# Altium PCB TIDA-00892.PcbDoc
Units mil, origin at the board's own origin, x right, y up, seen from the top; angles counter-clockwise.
Board outline 1220 x 522 mil, 4 copper layers (Top Layer, GND1, GND2, Bottom Layer), stack 63.756 mil thick; 26 components, 22 nets, 75 pads, 28 vias.
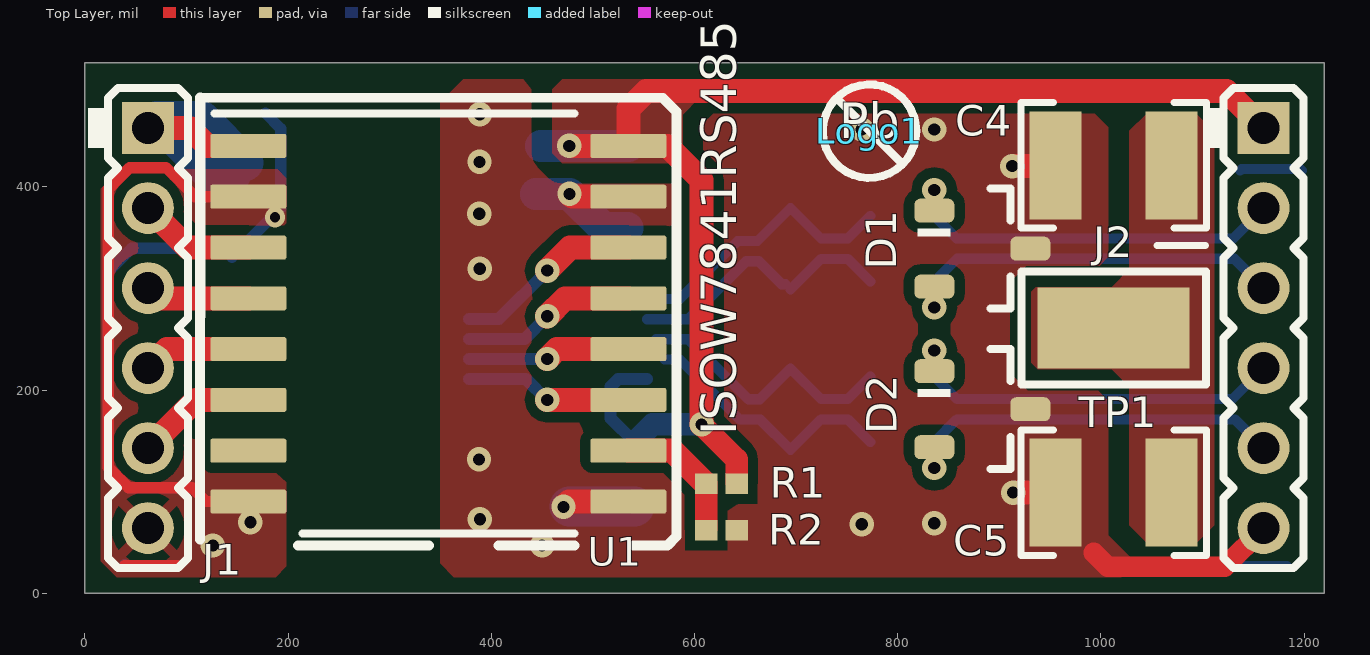
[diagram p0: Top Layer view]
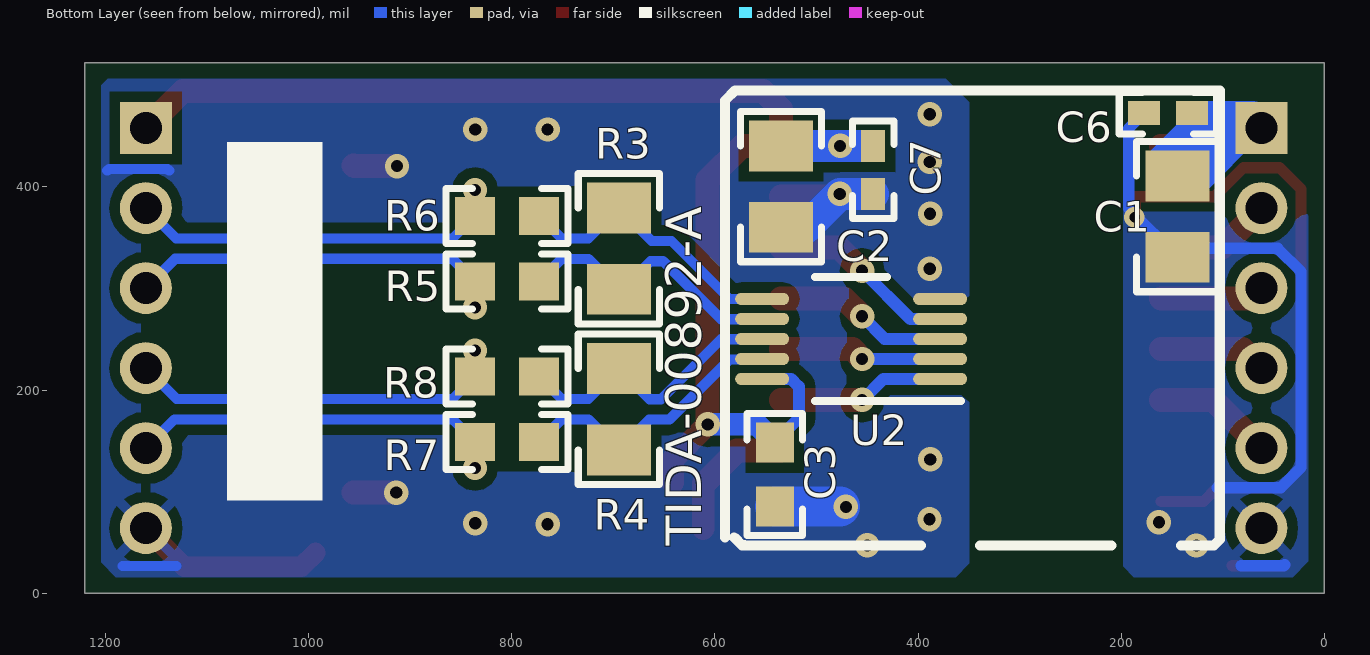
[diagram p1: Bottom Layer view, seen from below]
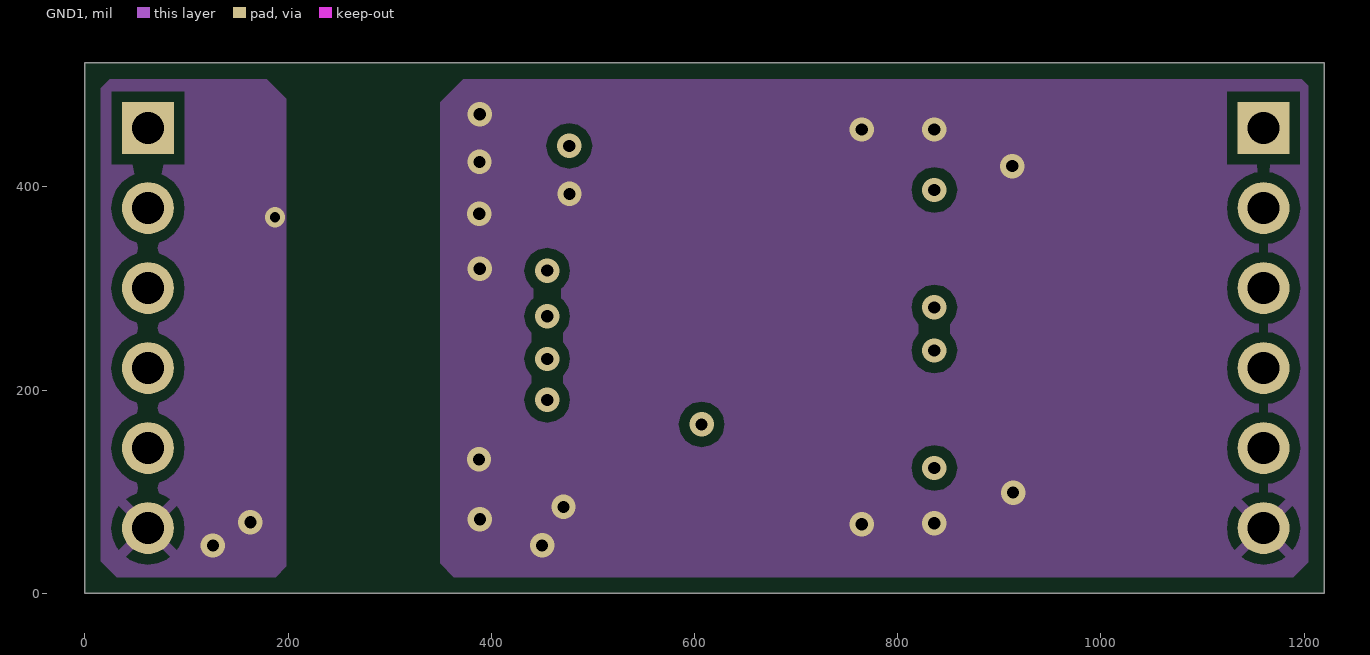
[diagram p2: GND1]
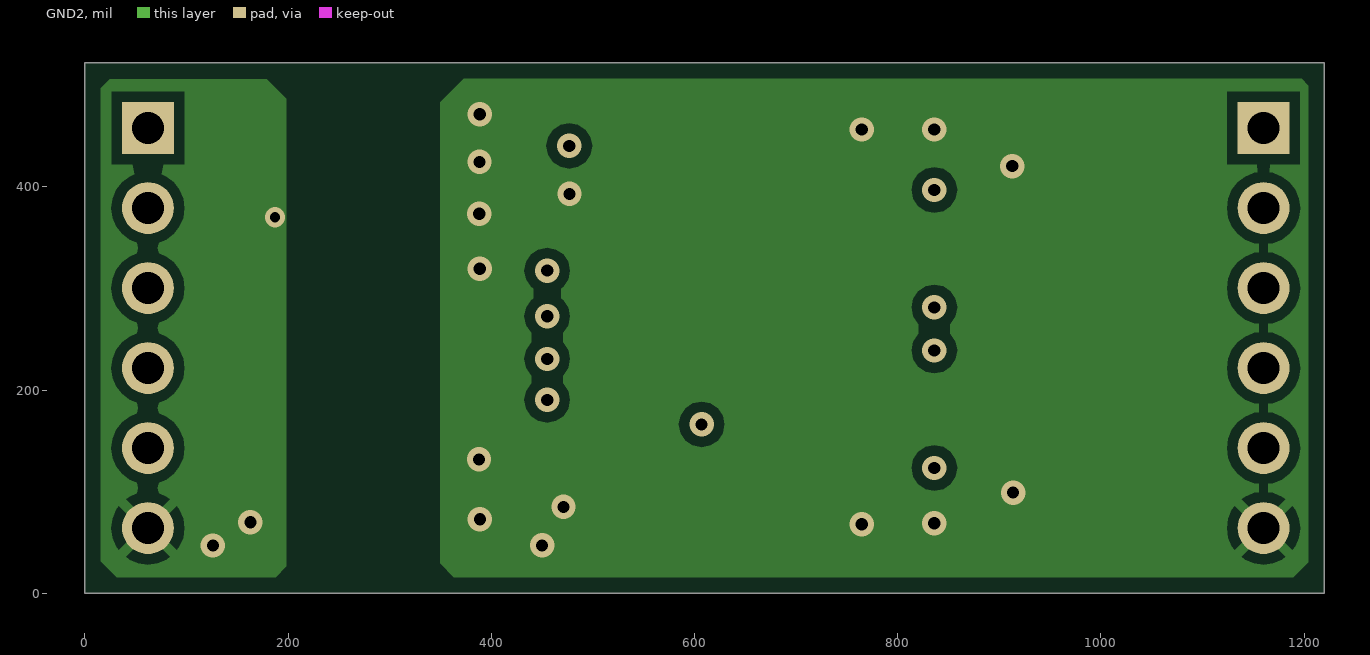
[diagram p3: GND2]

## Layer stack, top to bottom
Top Solder: solder mask 1, Solder Resist, Dk 3.5
Top Layer: signal copper 1.409
Dielectric1: core 21.26, FR-4, Dk 4.2
GND1: signal copper 0.709
Dielectric 3: prepreg 17, Dk 4.2
GND2: signal copper 0.709
Dielectric 2: core 21.26, Dk 4.2
Bottom Layer: signal copper 1.409
Bottom Solder: solder mask 1, Solder Resist, Dk 3.5

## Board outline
0,0 1220,0 1220,522 0,522

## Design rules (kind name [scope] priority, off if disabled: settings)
AcuteAngle [All] p1: minimum=4.50000000000000E+0001 checktracksonly=FALSE
AssemblyTestPointUsage [All] p1: valid=2
Clearance Clearance_1 [InNetClass('DIFF_120E') vs InNetClass('DIFF_120E')] p1: gap=10 except(7.87: Track-SMDPad SMDPad-SMDPad)
Clearance Clearance_Keepouts [((IsTrack Or IsArc) And Not InPoly) And IsFree and IsKeepOut vs ((IsTrack Or IsArc) And Not InPoly) And IsFree and IsKeepOut] p2: gap=0
Clearance Clearance_BoardEdge_MountingHoles [OnCopper and InComponentClass('Mounting Holes') vs IsKeepOut] p3: gap=40
Clearance Clearance_BoardEdge_Poly [OnCopper and InPoly vs IsKeepOut] p4: gap=25
Clearance Clearance_BoardEdge [OnCopper and Not InComponentClass('Logo') and not InComponentClass('FiducialMark') and not InRegion(1000,500,4000,800) and Not IsKeepout vs IsKeepOut] p5: gap=75
Clearance Clearance_Poly [InPolygon] p6: gap=25 except(10: Track-Poly SMDPad-Poly THPad-Poly Via-Poly; 20: Poly-Poly)
Clearance [All] p7: gap=7.87
ComponentClearance ComponentClearance_MountingHoles_FiducialMarks [InComponentClass('Mounting Holes') vs InComponentClass('FiducialMark')] p1: gap=50 collisioncheckmode=3 verticalgap=10 showdistances=FALSE
ComponentClearance ComponentClearance_Shunt [InComponentClass('Header') vs InComponentClass('Shunt')] p2: gap=0 collisioncheckmode=3 verticalgap=0 showdistances=FALSE
ComponentClearance ComponentClearance_Logo [InComponentClass('Logo')] p3: gap=50 collisioncheckmode=3 verticalgap=10 showdistances=FALSE
ComponentClearance ComponentClearance_ScrewToNut [(HasFootprint('NY PMS 440 0025 PH')) vs (HasFootprint('Keystone_1902C'))] p4: gap=5 collisioncheckmode=3 verticalgap=10 showdistances=FALSE
ComponentClearance ComponentClearance_MountingHoles [InComponentClass('Mounting Holes')] p5: gap=30 collisioncheckmode=3 verticalgap=100000 showdistances=FALSE
ComponentClearance ComponentClearance_SmallPassives [HasFootprint('0201*') or HasFootprint('0402*') or HasFootprint('0508') or HasFootprint('0603*') or HasFootprint('0612') or HasFootprint('0805*') or HasFootprint('0815*') or HasFootprint('0830*') or HasFootprint('1206*') or HasFootprint('1210*') or HasFootprint('1808*') or HasFootprint('1812*') or HasFootprint('1825*') or HasFootprint('2010*') or HasFootprint('2220*') or HasFootprint('2225*') or HasFootprint('2512*') or HasFootprint('2728*') or HasFootprint('3518*') vs HasFootprint('0201*') or HasFootprint('0402*') or HasFootprint('0508') or HasFootprint('0603*') or HasFootprint('0612') or HasFootprint('0805*') or HasFootprint('0815*') or HasFootprint('0830*') or HasFootprint('1206*') or HasFootprint('1210*') or HasFootprint('1808*') or HasFootprint('1812*') or HasFootprint('1825*') or HasFootprint('2010*') or HasFootprint('2220*') or HasFootprint('2225*') or HasFootprint('2512*') or HasFootprint('2728*') or HasFootprint('3518*')] p6: gap=20 collisioncheckmode=3 verticalgap=10 showdistances=FALSE
ComponentClearance ComponentClearance_THtoSMT [IsThruComponent vs IsSMTComponent] p7: gap=20 collisioncheckmode=3 verticalgap=30 showdistances=FALSE
ComponentClearance ComponentClearance_THtoTH [IsThruComponent vs IsThruComponent] p8: gap=20 collisioncheckmode=3 verticalgap=30 showdistances=FALSE
ComponentClearance [All] p9: gap=20 collisioncheckmode=3 verticalgap=10 showdistances=FALSE
DiffPairsRouting [InDifferentialPairClass('DIFF_120E')] p1: maxlimit=100 minlimit=10 mostfreqgap=10 toplayer_maxgap=10 toplayer_minwidth=10 toplayer_maxwidth=10 toplayer_prefwidth=10 midlayer1_minwidth=15 midlayer1_maxwidth=15 midlayer1_prefwidth=15 midlayer2_minwidth=15 midlayer2_maxwidth=15 midlayer2_prefwidth=15 bottomlayer_maxgap=10 bottomlayer_minwidth=10 bottomlayer_maxwidth=10 bottomlayer_prefwidth=10 maxuncoupledlength=1000
FabricationTestPointUsage TestPointUsage [All] p1: valid=2 allowmultiple=FALSE
FabricationTestpoint Testpoint [All] p1: side=3 testpointundercomponent=TRUE minsize=40 maxsize=100 preferedsize=60 minholesize=0 maxholesize=40 preferedholesize=32 testpointgrid=1 allowsidetop=TRUE allowsidebottom=TRUE usegrid=TRUE gridtolerance=0.01
FanoutControl Fanout_LCC [IsLCC] p1: bgadir=Out bgaviamode=Centered fanoutstyle=Auto fanoutdirection=Alternating viagrid=1 // Fanout_LCC (Default Rule)
FanoutControl Fanout_BGA [IsBGA] p2: bgadir=Out bgaviamode=Centered fanoutstyle=Auto fanoutdirection=Alternating viagrid=1 // Fanout_BGA (Default Rule)
FanoutControl Fanout_Default [All] p4: bgadir=Out bgaviamode=Centered fanoutstyle=Auto fanoutdirection=Alternating viagrid=1 // Fanout_Default (Default Rule)
FanoutControl Fanout_Small [(CompPinCount < 5)] p5: bgadir=Out bgaviamode=Centered fanoutstyle=Auto fanoutdirection=OutThenIn viagrid=1 // Fanout_Small (Default Rule)
HoleSize [All] p1: absolutevalues=TRUE maxlimit=251 minlimit=8 maxpercent=80.000 minpercent=20.000
MinimumAnnularRing MinimumAnnularRing_ThermalPadVias [IsVia and InAnyComponent] p1: minimumring=5.91
MinimumAnnularRing [All] p2: minimumring=5
MinimumSolderMaskSliver MinimumSolderMaskSliver_Logo [InComponentClass('Logo') vs InComponentClass('Logo')] p1: minsoldermaskwidth=0.7
MinimumSolderMaskSliver [All] p2: minsoldermaskwidth=3.94
PlaneConnect [InNet('GND2')] p1: planeconnectstyle=Relief reliefexpansion=10 reliefentries=4 reliefconductorwidth=10 reliefairgap=10
PolygonConnect PolygonConnect_1 [All vs HasFootprint('Harwin_M22-25106')] p1: connectstyle=Relief reliefconductorwidth=10 reliefentries=4 polygonreliefangle="45 Angle" airgapwidth=10
PolygonConnect [All] p2: connectstyle=Direct reliefconductorwidth=10 reliefentries=4 polygonreliefangle="90 Angle" airgapwidth=20
RoutingVias ThermalPadVias [IsVia and InAnyComponent] p1: holewidth=12 width=19.68 viastyle="Through Hole" minholewidth=12 minwidth=19 maxholewidth=12.99 maxwidth=30
RoutingVias [All] p2: holewidth=16 width=34 viastyle="Through Hole" minholewidth=7.87 minwidth=18 maxholewidth=40 maxwidth=65
SilkToBoardRegionClearance [Not ((IsComment or IsDesignator) And (Hide <> 'False')) and not InRegion(1000,500,4000,800)] p1:
SilkToSilkClearance SilkToSilkClearance_Pb-FreeLogo [(HasFootprint('Pb-Free_Overlay_Medium') OR HasFootprint('Pb-Free_Overlay_Small')) vs (HasFootprint('Pb-Free_Overlay_Medium') OR HasFootprint('Pb-Free_Overlay_Small'))] p1: silktosilkclearance=0
SilkToSilkClearance [All] p2: silktosilkclearance=3
SilkToSolderMaskClearance "Silk to Solder Mask Opening" [All] p1: minsilkscreentomaskgap=3 clearancetoexposedcopper=FALSE
SolderMaskExpansion [All] p1: expansion=1.97
Width DIFF_120E [InNetClass('DIFF_120E')] p1: maxlimit=4 minlimit=4 preferedwidth=4
Width [All] p2: maxlimit=100 minlimit=6 preferedwidth=10 checkconnectedcopper=TRUE
15 further rules are at their usual default settings.

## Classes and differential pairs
component class Header: J1 J2
component class TIDA-00892: C1 C2 C3 C4 C5 C6 C7 CL3 CR3 D1 D2 J1 J2 R1 R2 R3 R4 R5 R6 R7 R8 TP1 U1 U2
differential pair class DIFF_120E: D D_O R R_I
component class AssemblyNote: ZZ2 ZZ3 ZZ4
component class TIDA-00892_Hardware: !PCB Logo1 ZZ2 ZZ3 ZZ4
differential pair D_O: +D_O_P -D_O_N
differential pair D: +D_P -D_N
differential pair R_I: +R_I_P -R_I_N
differential pair R: +R_P -R_N

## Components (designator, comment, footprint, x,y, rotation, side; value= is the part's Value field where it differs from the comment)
C1 "GRM21BR6YA106KE43L" 0805_HV#1 144.84,370.75 r270 bottom
C2 "GRM21BR6YA106KE43L" 0805_HV#1 534.84,400.3 r270 bottom
C3 "GCM188R71H103KA37D" 0603#1 541,117 r270 bottom
C4 "202S41W472KV4E" 1210 1012.61,421.2 r0 top
C5 "202S41W472KV4E" 1210 1012.61,99.07 r0 top
C6 "GRM155R71E104KE14D" 0402 154,472.5 r0 bottom
C7 "GRM155R71E104KE14D" 0402 444.18,416.68 r270 bottom
D1 "CDSOT23-SM712" SOT-23#1 883.28,354.14 r180 top
D2 "CDSOT23-SM712" SOT-23#2 883.28,181.14 r0 top
J1 "M22-2510605" Harwin_M22-25106 62,261 r270 top
J2 "M22-2510605" Harwin_M22-25106 1160.08,261 r270 top
Logo1 "Pb-Free Symbol" Pb-Free_Overlay_Small 772.23,454.85 r0 top
R1 "ERJ-1GE0R00C" 0201M 626.43,107.81 r0 top
R2 "ERJ-1GE0R00C" 0201M 626.43,62.1 r0 top
R3 "ESR10EZPF1200" 0805_HV#2 674.45,339.14 r270 bottom
R4 "ESR10EZPF1200" 0805_HV#1 694.45,181.14 r270 bottom
R5 "CRCW060310R0JNEAHP" 0603#1 804.54,306.91 r0 bottom
R6 "CRCW060310R0JNEAHP" 0603#2 797.84,383.27 r0 bottom
R7 "CRCW060310R0JNEAHP" 0603#1 804.54,148.91 r0 bottom
R8 "CRCW060310R0JNEAHP" 0603#1 804.54,213.38 r0 bottom
TP1 "TESTPOINT" Keystone_5019 1012.63,261.04 r180 top
U1 "ISOW7841DW" DW0016B_N 347.84,265.3 r0 top
U2 "SN65HVD1473DGSR" DGS0010A_N 465.84,250.3 r0 bottom
ZZ2 "These assemblies are ESD sensitive, ESD precautions shall be observed." AssemblyNote 2226,964 r0 top
ZZ3 "These assemblies must be clean and free from flux and all contaminants. Use of no clean flux is not acceptable." AssemblyNote 2218,1092 r0 top
ZZ4 "These assemblies must comply with workmanship standards IPC-A-610 Class 2, unless otherwise specified." AssemblyNote 2225,1204 r0 top

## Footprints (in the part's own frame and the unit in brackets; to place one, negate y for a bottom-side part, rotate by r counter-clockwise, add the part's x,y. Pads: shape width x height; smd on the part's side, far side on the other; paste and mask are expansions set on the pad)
0201M [mm] "Data from Kemet datasheet CC101_COM dated 7/28/11"
  rect 0.56x0.52 smd mask+0.048: 1(-0.38,0) 2(0.38,0)
  body extent -0.31,-0.16 0.31,0.16, height 0.26
0402 [mm] "0402 from SM-752 data"
  rect 0.8x0.6 smd: 1(-0.6,0) 2(0.6,0)
  silkscreen extent -1.22,-0.52 1.22,0.52, body extent -0.55,-0.3 0.55,0.3, height 0.6
0603#1 [mm] "0603 from SM-752 data"
  rect 1x0.95 smd: 1(-0.8,0) 2(0.8,0)
  silkscreen extent -1.52,-0.69 1.52,0.69, body extent -0.87,-0.47 0.87,0.47, height 1
0603#2 [mm] "0603 from SM-752 data"
  rect 1x0.95 smd: 1(-0.63,0.302) 2(0.97,0.302)
  silkscreen extent -1.35,-0.39 1.69,0.99, body extent -0.7,-0.17 1.04,0.78, height 1
0805_HV#1 [mil] "0805 with 30mil clearance between pads"
  rect 50x63 smd: 1(-40,0) 2(40,0)
  silkscreen extent -74,-40 74,40, body extent -43,-29 43,29, height 57
0805_HV#2 [mil] "0805 with 30mil clearance between pads"
  rect 50x63 smd: 1(-40,-20) 2(40,-20)
  silkscreen extent -74,-60 74,20, body extent -43,-49 43,9, height 57
1210 [mm] "1210 from SM-752 data"
  rect 1.3x2.7 smd: 1(-1.45,0) 2(1.45,0)
  silkscreen extent -2.32,-1.57 2.32,1.57, body extent -1.7,-1.35 1.7,1.35, height 1.35
AssemblyNote [mil] "Assembly Note"
DGS0010A_N [mm] "TSSOP, 10-Leads, Body 3x3mm, Pitch 0.5mm, IPC Medium Density"
  oval 1.35x0.3 smd: 1(-2.225,1) 2(-2.225,0.5) 3(-2.225,0) 4(-2.225,-0.5) 5(-2.225,-1) 6(2.225,-1) 7(2.225,-0.5) 8(2.225,0) 9(2.225,0.5) 10(2.225,1)
  silkscreen extent -2.75,-1.55 0.9,1.55, body extent -2.45,-1.5 2.45,1.5, height 0.96
DW0016B_N [mm] "SOIC, 16-Leads, Body 10.5x7.6mm, Pitch 1.27mm, IPC Medium Density"
  rrect17% 1.9x0.6 smd: 1(-4.75,4.445) 2(-4.75,3.175) 3(-4.75,1.905) 4(-4.75,0.635) 5(-4.75,-0.635) 6(-4.75,-1.905) 7(-4.75,-3.175) 8(-4.75,-4.445) 9(4.75,-4.445) 10(4.75,-3.175) 11(4.75,-1.905) 12(4.75,-0.635) 13(4.75,0.635) 14(4.75,1.905) 15(4.75,3.175) 16(4.75,4.445)
  silkscreen extent -5.6,-5.25 3.4,5.25, body extent -5.17,-5.15 5.17,5.15, height 2.59
Harwin_M22-25106 [mm] "Header, 2mm, 6x1, TH"
  rect 1.3x1.3 hole 0.8: 1(-5,0)
  round 1.3 hole 0.8: 2(-3,0) 3(-1,0) 4(1,0) 5(3,0) 6(5,0)
  silkscreen extent -6,-1.5 6,1, body extent -6,-1 6,1, height 5
Keystone_5019 [mm] "Test Point, Miniature, SMT"
  rect 3.8x2.03 smd: 1(0,0)
  silkscreen extent -2.31,-1.42 2.31,1.42, body extent -1.9,-1.02 1.9,1.02, height 2.29
Pb-Free_Overlay_Small [mil]
  silkscreen extent -46,-46 46,46
SOT-23#1 [mm] "SOT23, 3-Leads, Body 2.9x1.3mm, Pitch 0.95mm, Lead Span 2.5mm, IPC Medium Density"
  rrect50% 1x0.6 smd: 1(1.2,-0.569) 2(1.2,1.331) 3(-1.2,0.381)
  silkscreen extent -0.7,-1.12 1.63,1.88, body extent -1.21,-1.07 1.16,1.83, height 1
SOT-23#2 [mm] "SOT23, 3-Leads, Body 2.9x1.3mm, Pitch 0.95mm, Lead Span 2.5mm, IPC Medium Density"
  rrect50% 1x0.6 smd: 1(-1.2,0.95) 2(-1.2,-0.95) 3(1.2,0)
  silkscreen extent -1.62,-1.5 0.7,1.5, body extent -1.16,-1.45 1.21,1.45, height 1

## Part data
C1 C2: "CAP, CERM, 10 µF, 35 V, +/- 10%, X5R, 0805"
C3: "CAP, CERM, 0.01 µF, 50 V, +/- 10%, X7R, AEC-Q200 Grade 1, 0603"
C4 C5: "CAP, CERM, 4700 pF, 2000 V, +/- 10%, X7R, 1210"
C6 C7: "CAP, CERM, 0.1 µF, 25 V, +/- 10%, X7R, 0402"
D1 D2: "Diode, TVS, Bi, 7 V, 400 W, SOT-23"
J1 J2: "Header, 2mm, 6x1, Gold, TH"
Logo1: library part Pb-Free
R1 R2: "RES, 0, 5%, 0.05 W, 0201"
R3 R4: "RES, 120, 1%, 0.4 W, 0805"
R5 R6 R7 R8: "RES, 10, 5%, 0.25 W, 0603"
TP1: library part 5019, "Test Point, Miniature, SMT"
U1: library part ISOW7841DWR, "ISOW7841DW, DW0016B"
U2: "3.3-V Full-Duplex RS-485 Transceiver With +/-16-kV IEC ESD, DGS0010A"
ZZ2 ZZ3 ZZ4: library part AssemblyNote

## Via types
v1: diameter 24, hole 12, Top Layer to Bottom Layer, tented both sides, 27 vias
v2: diameter 20, hole 10, Top Layer to Bottom Layer, tented both sides, 1 vias

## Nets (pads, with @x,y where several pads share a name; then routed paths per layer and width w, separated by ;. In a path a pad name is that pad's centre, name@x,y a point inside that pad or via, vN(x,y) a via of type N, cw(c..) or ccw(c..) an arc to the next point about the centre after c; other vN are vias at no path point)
D_N: R3.2 R5.1 U2.7 | length 269.2
  Bottom Layer w10: U2.7@553.44,269.67 593.81,269.67 650.87,326.73 663.27,326.73 685.86,304.14 R3.2@689.45,304.14 ; R3.2 724.45,329.14 750.81,329.14 R5.1
D_O_N: D1.2 J2.3 R5.2 | length 391.2
  Top Layer w10: v1(836.03,281.33) D1.2
  Bottom Layer w10: v1(836.03,281.33) R5.2 858.37,329.24 1131.21,329.24 J2.3
D_O_P: D1.1 J2.2 R6.2 | length 391.6
  Top Layer w10: D1.1 v1(836.03,396.95)
  Bottom Layer w10: v1(836.03,396.95) R6.2 858.17,349.24 1130.21,349.24 J2.2
D_P: R3.1 R6.1 U2.6 | length 278.3
  Bottom Layer w10: U2.6 585.52,289.67 642.59,346.73 662.04,346.73 R3.1 724.45,349.14 750.81,349.14 R6.1
GND: C4.2 C5.2 TP1.1
GND1: C1.2 C6.2 J1.6 U1.2 U1.8 | length 1305.7
  Top Layer w11: 39,27 91,27 ; U1.8 119.1,90.3 105.47,103.93 42.83,103.93 23.04,123.72 23.04,397.64 22.97,397.7 44.15,418.89 79.8,418.89 108.39,390.3 U1.2 186.16,390.3 v2@186.16,375.59
  Bottom Layer w11: 22.97,316.51 46.02,339.56 136.03,339.56 C1.2 192.67,378.58 192.67,457.45 C6.2 ; 23.04,316.44 23.04,123.86 42.97,103.93 105.47,103.93 ; 39,28 40,27 82,27
  other v1: 126,47 162.91,69.98
  other v2: 187.08,370.11
GND2: C2.2 C3.2 C4.1 C5.1 C7.2 D1.3 D2.3 J2.6 R2.2 U1.9 U1.15 U2.5 | length 679.1
  Top Layer w20: 993,40 1006.86,26.14 1035.66,26.14 1050.06,26.14 1078.87,26.14 1093.27,26.14 1122.07,26.14 J2.6
  Top Layer w23.62: v1(471,85) 476.3,90.3 U1.9 ; v1(477,393.06) 479.76,390.3 U1.15 ; v1(912.81,420.41) 954.73,420.41 C4.1 ; v1@915.61,99.07 C5.1
  Bottom Layer w10: 1130,27 1183,27 ; 1137,416 1138.57,417.57 1196.43,417.57 1198,416
  Bottom Layer w22: v1@474.24,393.05 474.77,393.58 v1@475.9,392.45
  Bottom Layer w31.5: C7.2 v1@474.24,393.05 ; v1(477,393.06) 510.76,359.3 C2.2@533.84,359.3
  Bottom Layer w39.37: v1@477,85.5 C3.2
  other v1: 450,47.14 764.63,68.01 835.87,68.96 388.72,72.87 913.61,99.07 387.93,131.74 388.54,319.42 388.08,373.49 388.42,424.59 764.63,456.5 835.87,456.5 388.54,471.4
NetJ1_2: J1.2 U1.3 | length 114.9
  Top Layer w23.62: J1.2 100.81,340.3 U1.3
NetJ1_3: J1.3 U1.4 | length 103
  Top Layer w23.62: J1.3 72.07,290.3 U1.4
NetJ1_4: J1.4 U1.5 | length 108.4
  Top Layer w9: J1.4@60,241.63 J1.4@61.33,240.3
  Top Layer w23.62: J1.4 80.67,240.3 U1.5
NetJ1_5: J1.5 U1.6 | length 118.5
  Top Layer w23.62: J1.5 109.41,190.3 U1.6
NetR1_1: R1.1 R2.1 U1.10 | length 133.6
  Top Layer w22.05: R2.1@611.47,63.5 R1.1
  Top Layer w23.62: U1.10 578.2,140.3 R1.1@610.68,107.81
NetU1_11: U1.11 U2.1 | length 165.1
  Top Layer w23.62: v1(455,190.3) U1.11
  Bottom Layer w11.81: U2.1 434.09,210.93 v1@454.92,190.11
NetU1_12: U1.12 U2.2 | length 160.3
  Top Layer w23.62: v1(455,230.61) 464.69,240.3 U1.12
  Bottom Layer w11.81: U2.2 v1@454.64,230.61
NetU1_13: U1.13 U2.3 | length 173.1
  Top Layer w23.62: v1(455,272.61) 472.69,290.3 U1.13
  Bottom Layer w11.81: U2.3 432.82,250.3 v1@455,272.48
NetU1_14: U1.14 U2.4 | length 185.7
  Top Layer w23.62: v1(455,317.61) 477.69,340.3 U1.14
  Bottom Layer w11.81: U2.4 407.37,269.98 v1(455,317.61)
R_I_N: D2.1 J2.4 R8.2 | length 391.9
  Top Layer w10: D2.1 v1(836.03,238.95)
  Bottom Layer w10: v1(836.03,238.95) R8.2 858.27,191.14 1129.59,191.14 J2.4
R_I_P: D2.2 J2.5 R7.2 | length 390.9
  Top Layer w10: v1(836.03,123.33) D2.2
  Bottom Layer w10: v1(836.03,123.33) R7.2 858.27,171.14 1131.83,171.14 J2.5
R_N: R4.1 R8.1 U2.8 | length 268.3
  Bottom Layer w10: U2.8@562.27,250 593.93,250 653.04,190.9 664.2,190.9 R4.1@693.65,220.35 ; R4.1 724.45,191.14 750.81,191.14 R8.1
R_P: R4.2 R7.1 U2.9 | length 260.9
  Bottom Layer w10: U2.9@570.56,230 585.65,230 644.75,170.9 664.69,170.9 R4.2 724.45,171.14 750.81,171.14 R7.1
VIN: C1.1 C6.1 J1.1 U1.1 | length 325
  Top Layer w23.62: J1.1 103.04,457.85 120.59,440.3 U1.1
  Bottom Layer w36: J1.1 J1.1@79.48,457.85 ; C1.1 126.59,410.75 J1.1@79.48,457.85 ; C1.1@157.77,423.68 115.07,466.38 70.96,466.38 J1.1@79.48,457.85
VOUT: C2.1 C3.1 C7.1 J2.1 R1.2 U1.16 U2.10 | length 1408.9
  Top Layer w22.05: v1(607,166.18) 641.39,131.79 R1.2@641.39,108.7
  Top Layer w23.62: v1@477,440 477.3,440.3 U1.16 ; v1(607,166.18) 607,406.73 573.43,440.3 U1.16 ; J2.1 1123.54,494.39 552.57,494.39 534.85,476.67 U1.16
  Bottom Layer w11.81: C3.1 517.27,172.23 517.27,203.37 524.83,210.93 U2.10
  Bottom Layer w22: v1(476.7,440.3) 478.7,438.3 v1@480.7,440.3 ; C3.1 558.68,166.18 v1(607,166.18)
  Bottom Layer w31.5: C7.1@449,440.3 v1(476.7,440.3) ; v1@477,440.3 480.7,440.3 C2.1
pads on no net: U1.7

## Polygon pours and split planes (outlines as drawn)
GND on Top Layer "GND_L01_P039" (solid, remove dead copper, pour order 39): 931.25,226.91 931.25,296.71 935.89,301.34 1010.63,301.34 1028.14,318.85 1028.14,455.02 1046.61,473.49 1092.73,473.49 1111.57,454.65 1111.57,66.84 1094.74,50.01 1044.85,50.01 1028.14,66.73 1028.14,203.32 1010.91,220.55 937.61,220.55
GND1 on Top Layer "GND1_L01_P027" (solid, remove dead copper, pour order 27): 34.93,417.38 189.56,417.38 198.23,408.7 198.23,26.5 187.73,16 31.21,16 15.73,31.48 15.73,398.17
GND2 on Top Layer "GND2_L01_P017" (solid, remove dead copper, pour order 17): 372.57,506.1 349.63,483.17 349.63,29.48 363.11,16 1020,16 1029.57,25.57 1029.57,34.81 1007.42,56.96 1007.42,189.47 997.47,199.43 928.15,199.43 910.43,217.14 910.43,306.27 926.59,322.43 998.69,322.43 1007.42,331.16 1007.42,458.52 959.84,506.1
VOUT on Top Layer "VOUT_L01_P012" (solid, pour order 12): 470,506.1 459.91,496.01 459.91,433.22 469.89,423.24 574.92,423.24 588.22,436.54 588.21,470.89 604.85,487.52 604.85,498.43 597.18,506.1
GND2 on GND1 "GND2_L02_P021" (solid, remove dead copper, pour order 21): 372.55,506.16 349.63,483.25 349.63,29.47 363.11,16 1189.52,16 1204,30.48 1204,499.66 1197.49,506.16
GND1 on GND1 "GND1_L02_P029" (solid, remove dead copper, pour order 29): 24.64,506.01 178.99,506.01 198.23,486.77 198.23,26.5 187.73,16 31.21,16 15.73,31.48 15.73,497.1
GND2 on GND2 "GND2_L03_P023" (solid, remove dead copper, pour order 23): 372.68,506.22 349.63,483.17 349.63,29.47 363.11,16 1189.52,16 1204,30.48 1204,499.66 1197.44,506.22
GND1 on GND2 "GND1_L03_P031" (solid, remove dead copper, pour order 31): 24.64,506.01 178.99,506.01 198.23,486.77 198.23,26.5 187.74,16 31.21,16 15.73,31.48 15.73,497.1
GND1 on Bottom Layer "GND1_L04_P033" (solid, remove dead copper, pour order 33): 61.53,426.78 157.96,426.78 198.24,386.51 198.23,26.5 187.74,16 31.21,16 15.73,31.48 15.73,380.99
GND2 on Bottom Layer "GND2_L04_P025" (solid, remove dead copper, pour order 25): 372.68,506.22 349.63,483.17 349.63,29.47 363.11,16 1189.52,16 1204,30.48 1204,502 1199.78,506.22
no net on Bottom Solder "NONET_L-01_P-001" (solid): 354.73,51.01 386.51,51.01 388.7,48.82 388.7,22.91 386.53,20.75 359.38,20.75 352.53,27.59 352.53,48.81
no net on Bottom Solder "NONET_L-01_P-001" (solid): 164.4,51.01 194.39,51.01 197.47,47.92 197.48,26.44 191.51,20.48 163.92,20.48 161.19,23.21 161.19,47.81
no net on Bottom Paste "NONET_L-01_P-001" (solid): 354.73,51.01 386.51,51.01 388.72,48.8 388.72,22.94 386.53,20.75 359.38,20.75 352.53,27.59 352.53,48.81
no net on Bottom Paste "NONET_L-01_P-001" (solid): 164.39,51.01 194.39,51.01 197.48,47.92 197.48,26.44 191.51,20.48 163.92,20.48 161.19,23.21 161.19,47.81
no net on Top Solder "NONET_L-01_P-001" (solid): 164.4,51.01 194.39,51.01 197.48,47.92 197.48,26.44 191.51,20.48 163.92,20.48 161.19,23.21 161.19,47.81
no net on Top Solder "NONET_L-01_P-001" (solid): 354.73,51.01 386.5,51.01 388.72,48.79 388.72,22.94 386.53,20.75 359.38,20.75 352.56,27.57 352.56,48.83
no net on Top Paste "NONET_L-01_P-001" (solid): 164.4,51.01 194.39,51.01 197.48,47.92 197.48,26.44 191.51,20.48 163.92,20.48 161.19,23.21 161.19,47.81
no net on Top Paste "NONET_L-01_P-001" (solid): 354.73,51.01 386.51,51.01 388.72,48.8 388.72,22.94 386.53,20.75 359.38,20.75 352.56,27.56 352.56,48.83

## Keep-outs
Keep-Out Layer:
  text ".Layer_Name" at 577,-858.49 h60

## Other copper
Top Layer:
  text ".Layer_Name" at 577,-858.49 h60
GND1:
  text ".Layer_Name" at 577,-858.49 h60
GND2:
  text ".Layer_Name" at 577,-858.49 h60
Bottom Layer:
  text ".Layer_Name" at 577,-858.49 h60

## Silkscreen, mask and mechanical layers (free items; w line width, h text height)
Top Overlay:
  lines w7: 1055.37,342.17 1102.87,342.17
  lines w10: 113.2,53.22 113.45,488.08 ; 113.85,488.08 568.74,487.43 582.22,474 582.22,56 573.53,47.32 540,47.12 ; 209.79,47.1 338.82,47.09 ; 407,47 482,47
  text "ISOW7841RS485" at 652.95,155.6 h60 r90
  text ".Layer_Name" at 577,-858.49 h60
Bottom Overlay:
  region: 986.15,444.37 986.15,91.37 1080.15,91.37 1080.15,444.37
  lines w10: 140.98,47 109,47 103,53 103,495 579.98,495 590,484.98 590,55 ; 209.79,47.1 338.82,47.09 ; 396.97,47.12 570.99,47.19 ; 573,47 581,55
  text "TIDA-00892-A" at 601.45,46.96 h60 r270
  text ".Layer_Name" at 577,-858.49 h60
Top Paste:
  text ".Layer_Name" at 577,-858.49 h60
Bottom Paste:
  text ".Layer_Name" at 577,-858.49 h60
Top Solder:
  text ".Layer_Name" at 577,-858.49 h60
  text ".Layer_Name" at 577,-858.49 h60
Bottom Solder:
  text ".Layer_Name" at 577,-858.49 h60
Drill Guide:
  text ".Layer_Name" at 577,-858.49 h60
M1 Board Outline:
  the board outline again, w7
M2 Board Dimensions:
  rectangle: 125,-400 500,-275
  rectangle: 0,-275 125,-150
  lines w7: 0,-275 1000,-275 ; 125,-400 125,-150 ; 250,-400 250,-150 ; 500,-400 500,-150 ; 750,-400 750,-150 ; 0,-400 0,-150 1000,-150 1000,-400 0,-400
M3 3D STEP Top:
  text ".Layer_Name" at 577,-858.49 h60
M4 3D STEP Bottom:
  text ".Layer_Name" at 577,-858.49 h60
M5 Assembly Top:
  lines w10: -292,-930.17 6308,-930.17 ; -292,-726.83 6310,-726.83 ; -292,-523.5 -292,-1133.5 3713,-1133.5 6310,-1133.5 6310,-523.5 -291.5,-523.5 -291.5,-1133.5 1284,-1133.5 ; 2173,-1133.5 2173,-523.5 ; 3440,-726.83 3440,-523.5 ; 4280,-726.83 4280,-523.5 ; 4902,-1140 4902,-937.17
  text "COMPONENTS MARKED 'DNP' SHOULD NOT BE POPULATED." at 1153.5,-318.5 h60
  text "ASSEMBLY VARIANT:" at 1153,-434 h60
  text ".VariantName" at 2189,-434 h60
  text "BOARD #:" at 2248,-655.67 h60
  text "TIDA-00892" at 2793.5,-655.67 h60
  text "REV:" at 3638,-655.67 h60
  text ".PCB_Rev" at 3929.5,-655.67 h60
  text "SVN REV:" at 4476,-655.67 h60
  text ".VersionControl_RevNumber" at 4982,-655.67 h60
  text "Assembly Top" at 551.79,-847.48 h60
  text "PLOT NAME =" at -228.5,-1064.34 h60
  text ".plot_File_Name" at 577,-1064.34 h60
  text "GENERATED    :" at 2250,-1064.34 h60
  text ".Print_Date" at 3119.5,-1064.34 h60
  text ".Print_Time" at 3848.5,-1064.34 h60
  text "TEXAS INSTRUMENTS" at 5113,-1064.34 h60
M6 Assembly Bottom:
  lines w10: -292.5,-727.33 6309.5,-727.33 ; -290.5,-930.67 6309.5,-930.67 ; 1115.5,-1140.5 1115.5,-937.67 ; 1737.5,-727.33 1737.5,-524 ; 2577.5,-727.33 2577.5,-524 ; 3844.5,-1134 3844.5,-524 ; 4733.5,-1134 6309,-1134 6309,-524 -292.5,-524 -292.5,-1134 2304.5,-1134 6309.5,-1134 6309.5,-524
  text "COMPONENTS MARKED 'DNP' SHOULD NOT BE POPULATED." at 6102,-318 h60
  text ".VariantName" at 5058,-434 h60
  text "ASSEMBLY VARIANT:" at 6097,-434 h60
  text ".VersionControl_RevNumber" at 1035.5,-656.17 h60
  text "SVN REV:" at 1541.5,-656.17 h60
  text ".PCB_Rev" at 2088,-656.17 h60
  text "REV:" at 2379.5,-656.17 h60
  text "TIDA-00892" at 3224,-656.17 h60
  text "BOARD #:" at 3769.5,-656.17 h60
  text "PCB VIEWED FROM BOTTOM SIDE" at 6246,-656.17 h60
  text "Assembly Bottom" at 5508.64,-850.92 h60
  text "TEXAS INSTRUMENTS" at 904.5,-1064.84 h60
  text ".Print_Time" at 2169,-1064.84 h60
  text ".Print_Date" at 2898,-1064.84 h60
  text "GENERATED    :" at 3767.5,-1064.84 h60
  text ".plot_File_Name" at 5440.5,-1064.84 h60
  text "PLOT NAME =" at 6246,-1064.84 h60
M9 Title Sheet:
  drawing of 57 lines, arcs and shapes, not listed
  text "1" at 739.84,8036.5 h70
  text "2" at 3235.5,8036.5 h70
  text "3" at 5724.84,8036.5 h70
  text "4" at 8231.51,8036.5 h70
  text "5" at 10730.5,8036.5 h70
  text "6" at 13235.5,8036.5 h70
  text "A" at -416.5,6893.5 h70
  text "A" at 14383.5,6893.5 h70
  text "B" at -416.5,4513.5 h70
  text "B" at 14383.5,4513.5 h70
  text "C" at -416.5,2138.5 h70
  text "C" at 14383.5,2138.5 h70
  text "PROJECT TITLE:" at 11343.5,277.5 h45
  text ".PRJ_Title" at 11393.5,144.17 h70
  text "DESIGNED FOR:" at 11343.5,-23.5 h45
  text ".PRJ_Customer" at 11393.5,-163.5 h70
  text "D" at -416.5,-231.5 h70
  text "D" at 14383.5,-231.5 h70
  text "FILE NAME:" at 11343.5,-323.5 h45
  text ".PCB_File_Name_No_Path" at 11393.5,-443.5 h70
  text "Texas Instruments (TI) and/or its licensors do not warrant the accuracy or completeness of this specification" at 6374,-605.34 h45
  text "ENGINEER:" at 11343.5,-613.5 h45
  text "LAYOUT BY:" at 12848.5,-613.5 h45
  text "or any information contained therein. TI and/or its licensors do not warrant that this design will meet" at 6329.01,-718 h45
  text ".PRJ_Engineer" at 11393.5,-768.49 h70
  text ".PCB_Layout" at 12899,-768.49 h70
  text "the specifications, will be suitable for your application or fit for any particular purpose, or will operate in" at 6329.01,-830.67 h45
  text "ALTIUM DESIGNER VERSION:" at 12848.5,-923.5 h45
  text "an implementation. TI and/or its licensors do not warrant that the design is production worthy. You should" at 6329.01,-943.33 h45
  text "completely validate and test your design implementation to confirm the system functionality for your application." at 6374,-1056 h45
  text ".print_Scale" at 11393.5,-1056.83 h70
  text ".Application_BuildNumber" at 12899,-1056.83 h70
  text "1" at 739.84,-1263.5 h70
  text "2" at 3235.5,-1263.5 h70
  text "3" at 5724.84,-1263.5 h70
  text "4" at 8231.51,-1263.5 h70
  text "5" at 10730.5,-1263.5 h70
  text "6" at 13235.5,-1263.5 h70
M10 Fab Notes:
  drawing of 185 lines, arcs and shapes, not listed
  text "DESIGN INFORMATION" at 12381.02,5910 h60
  text "MIN. TRACK WIDTH:" at 11736.46,5730 h60
  text "9" at 12832.7,5730 h60
  text "MIL" at 12987.46,5730 h60
  text "MIN. CLEARANCE:" at 11736.46,5598 h60
  text "0.2" at 12772.7,5598 h60
  text "mm" at 12987.46,5598 h60
  text "MIN. VIA PAD SIZE:" at 11736.46,5466 h60
  text "24" at 12802.71,5466 h60
  text "MIL" at 12987.46,5466 h60
  text "0.05mm (2MIL)" at 12431.46,5324.29 h60
  text "MINIMUM ANNULAR RING" at 11407.23,5320 h60
  text "EXTERNAL" at 13139.46,5320 h60
  text "PER" at 11607.23,5202 h60
  text "IPC-D-275 CLASS 2 LEVEL C" at 11827.23,5202 h60
  text "MIL, HOLES" at 13315.46,5089.71 h60
  text "+/-" at 12923,5089 h60
  text "+/-" at 13777,5089 h60
  text "REGISTRATION TOLERANCES:" at 11407.23,5084 h60
  text "METAL" at 12607,5084 h60
  text "5" at 13183.2,5084 h60
  text "3" at 14016.2,5084 h60
  text "MIL" at 14132.46,5084 h60
  text "MATERIAL:" at 11332.46,4874.54 h60
  text "FR-4 High Tg" at 12318.9,4734.21 h60
  text "FR-408" at 11753.46,4725.64 h60
  text "X" at 12165.46,4725.64 h60
  text "OTHER" at 13241.46,4725.64 h60
  text "62 MIL (1.6mm) +/-10%" at 12073.56,4562.92 h60
  text "THICKNESS:" at 11407.23,4558.64 h60
  text "X" at 11945.4,4558.64 h60
  text "OTHER" at 13358.46,4558.64 h60
  text "TOLERANCE:" at 11407.23,4400.64 h60
  text "X" at 12246.53,4400.64 h60
  text "ANSI IPC-6012 TYPE 3 CLASS 2" at 12433.48,4400.64 h60
  text "OTHER +/-" at 12433.46,4244.64 h60
  text "BOW & TWIST:" at 11407.23,4087.64 h60
  text "X" at 12246.53,4087.64 h60
  text "ANSI IPC-6012 TYPE 3 CLASS 2" at 12433.48,4087.64 h60
  text "OTHER +/-" at 12433.46,3929.13 h60
  text "DRILLING:" at 11332.46,3790.64 h60
  text "REFERENCE:" at 11407.23,3673.64 h60
  text "X" at 12055.46,3673.64 h60
  text "AS SHOWN" at 12242.46,3673.64 h60
  text "X" at 12956.46,3673.64 h60
  text "NC_DRILL FILES" at 13093.46,3673.64 h60
  text "PTH MIN COPPER THICKNESS:" at 11407.23,3515.64 h60
  text "X" at 12757.46,3515.64 h60
  text "1MIL" at 12894.46,3515.64 h60
  text "OTHER" at 13391.46,3515.64 h60
  text "BOARD FINISH:" at 11332.46,3356.64 h60
  text "SILKSCREEN:" at 11487.68,3238.64 h60
  text "X" at 12436.46,3238.64 h60
  text "TOP" at 12562.46,3238.64 h60
  text "X" at 12946.46,3238.64 h60
  text "BOTTOM" at 13073.46,3238.64 h60
  text "SILKSCREEN COLOR:" at 11487.68,3071.64 h60
  text "X" at 12435.42,3071.64 h60
  text "WHITE" at 12562.46,3071.64 h60
  text "OTHER" at 13073.46,3071.64 h60
  text "SOLDER RESIST COLOR:" at 11487.68,2901.64 h60
  text "X" at 12055.42,2742.44 h60
  text "GREEN" at 12182.46,2742.44 h60
  text "BLUE" at 12773.46,2742.44 h60
  text "OTHER" at 13311.46,2742.44 h60
  text "IMMERSION GOLD (ENIG)" at 12393.46,2553.92 h60
  text "ENEPIG" at 13731,2550.64 h60
  text "SURFACE FINISH:" at 11332.46,2549.64 h60
  text "X" at 12206.51,2549.64 h60
  text "IMM. TIN/SILVER OR EQUIV" at 11662,2392.64 h60
  text "OTHER" at 13093.46,2392.64 h60
  text "ARRAY/PANEL:" at 11332.46,2213.64 h60
  text "CUT AND TRIM PER MECH LAYER 1" at 12393.46,2209.35 h60
  text "N.C. ROUTE" at 12393.46,2057.64 h60
  text "X" at 13072.46,2057.64 h60
  text "V. SCORE" at 13259.46,2057.64 h60
  text "CERTIFICATION:" at 11332.46,1920.64 h60
  text "MATERIALS AND WORKMANSHIP FOR ALL PCBS" at 12057.46,1920.64 h60
  text "TO MEET OR EXCEED THE REQUIREMENTS OF:" at 12057.46,1822.64 h60
  text "X" at 11683.96,1686.13 h60
  text "ANSI IPC-A-600F CLASS ->" at 11822.96,1686.13 h60
  text "X" at 13462.02,1686.13 h60
  text "2" at 13580.96,1686.14 h60
  text "1" at 13265.96,1684.64 h60
  text "3" at 13934.96,1684.64 h60
  text "X" at 11686.02,1526.64 h60
  text "UL 94V-0" at 11822.96,1526.64 h60
  text "X" at 12498.02,1526.64 h60
  text "RoHS" at 12634.96,1526.64 h60
  text "OTHER" at 13279.36,1526.64 h60
  text "PER ORDER" at 13676.42,1526.64 h60
  text "ADDITIONAL REQUIREMENTS:" at 11332.46,1385.64 h60
  text "MICROSECTION:" at 11407.23,1270.64 h60
  text "YES" at 12312.96,1270.64 h60
  text "REQUIRED" at 13174.46,1114.49 h60
  text "BARE BOARD ELEC. TEST:" at 11407.23,1111.64 h60
  text "NONE" at 12712.96,1111.64 h60
  text "X" at 13047.46,1111.64 h60
  text "PER ORDER" at 13766.46,1111.64 h60
  text "MANUFACTURER'S UL:" at 11407.23,954.64 h60
  text "RAIL" at 12572.96,950.35 h60
  text "METAL" at 13064.77,950.35 h60
  text "X" at 13440,950 h60
  text "SILK" at 13576.46,950.35 h60
M11 Gerber Information:
  lines w10: -292,-930.17 6308,-930.17 ; -292,-726.83 6310,-726.83 ; -292,-523.5 -292,-1133.5 3713,-1133.5 6310,-1133.5 6310,-523.5 -291.5,-523.5 -291.5,-1133.5 1284,-1133.5 ; 2173,-1133.5 2173,-523.5 ; 3440,-726.83 3440,-523.5 ; 4280,-726.83 4280,-523.5 ; 4902,-1140 4902,-937.17
  text "ALL ARTWORK VIEWED FROM TOP SIDE" at -228.5,-655.67 h60
  text "BOARD #:" at 2248,-655.67 h60
  text "TIDA-00892" at 2793.5,-655.67 h60
  text "REV:" at 3638,-655.67 h60
  text ".PCB_Rev" at 3929.5,-655.67 h60
  text "SVN REV:" at 4476,-655.67 h60
  text ".VersionControl_RevNumber" at 4982,-655.67 h60
  text "LAYER NAME =" at -228.5,-858.49 h60
  text "PLOT NAME =" at -228.5,-1064.34 h60
  text ".plot_File_Name" at 577,-1064.34 h60
  text "GENERATED    :" at 2250,-1064.34 h60
  text ".Print_Date" at 3119.5,-1064.34 h60
  text ".Print_Time" at 3848.5,-1064.34 h60
  text "TEXAS INSTRUMENTS" at 5113,-1064.34 h60
M12 Stackup:
  drawing of 295 lines, arcs and shapes, not listed
  text "Layer" at 9733.5,7669.5 h60
  text "Name" at 10143.41,7669.5 h60
  text "Material" at 11073.16,7669.5 h60
  text "Thickness" at 11932.92,7669.5 h60
  text "Constant" at 12582.76,7669.5 h60
  text "Board Layer Stack" at 13152.62,7669.5 h60
  text "1" at 9733.5,7549.5 h60
  text "Top Overlay" at 10143.41,7549.5 h60
  text "2" at 9733.5,7429.5 h60
  text "Top Solder" at 10143.41,7429.5 h60
  text "Solder Resist" at 11073.16,7429.5 h60
  text "1.00mil" at 11932.92,7429.5 h60
  text "3.5" at 12582.76,7429.5 h60
  text "3" at 9733.5,7309.5 h60
  text "Top Layer" at 10143.41,7309.5 h60
  text "Copper" at 11073.16,7309.5 h60
  text "1.41mil" at 11932.92,7309.5 h60
  text "4" at 9733.5,7189.5 h60
  text "Dielectric1" at 10143.41,7189.5 h60
  text "FR-4" at 11073.16,7189.5 h60
  text "21.26mil" at 11932.92,7189.5 h60
  text "4.2" at 12582.76,7189.5 h60
  text "5" at 9733.5,7069.5 h60
  text "GND1" at 10143.41,7069.5 h60
  text "Copper" at 11073.16,7069.5 h60
  text "0.71mil" at 11932.92,7069.5 h60
  text "6" at 9733.5,6949.5 h60
  text "Dielectric 3" at 10143.41,6949.5 h60
  text "17.00mil" at 11932.92,6949.5 h60
  text "4.2" at 12582.76,6949.5 h60
  text "7" at 9733.5,6829.5 h60
  text "GND2" at 10143.41,6829.5 h60
  text "Copper" at 11073.16,6829.5 h60
  text "0.71mil" at 11932.92,6829.5 h60
  text "8" at 9733.5,6709.5 h60
  text "Dielectric 2" at 10143.41,6709.5 h60
  text "21.26mil" at 11932.92,6709.5 h60
  text "4.2" at 12582.76,6709.5 h60
  text "9" at 9733.5,6589.5 h60
  text "Bottom Layer" at 10143.41,6589.5 h60
  text "Copper" at 11073.16,6589.5 h60
  text "1.41mil" at 11932.92,6589.5 h60
  text "10" at 9733.5,6469.5 h60
  text "Bottom Solder" at 10143.41,6469.5 h60
  text "Solder Resist" at 11073.16,6469.5 h60
  text "1.00mil" at 11932.92,6469.5 h60
  text "3.5" at 12582.76,6469.5 h60
  text "11" at 9733.5,6349.5 h60
  text "Bottom Overlay" at 10143.41,6349.5 h60
  text "10Mil Trace and 10Mil Spacing traces are 120- Ohm Differential Trace." at 1628,80 h60
M13 Component Bodies Top:
  text ".Layer_Name" at 577,-858.49 h60
M14 Component Bodies Bottom:
  text ".Layer_Name" at 577,-858.49 h60
M15 Courtyards Top:
  text ".Layer_Name" at 577,-858.49 h60
M16 Courtyards Bottom:
  text ".Layer_Name" at 577,-858.49 h60
Drill Drawing:
  circle w10: c4776.51,2005.08 r27.66
  lines w10: 4748.86,1728.5 4804.17,1728.5 4804.17,1783.82 4748.86,1783.82 4748.86,1728.5 ; 4748.86,1880.62 4776.51,1852.96 4804.17,1880.62 4776.51,1908.28 4748.86,1880.62
  lines w12: 4698.71,1691.17 6678.11,1691.17 ; 4698.71,2064.54 6678.11,2064.54 ; 5036.88,1566.71 5036.88,2189 ; 5369,1566.71 5369,2189 ; 6006,1566.71 6006,2189 ; 6265.35,1566.71 6265.35,2189 ; 4698.71,1566.71 6678.11,1566.71 6678.11,2189 4698.71,2189 4698.71,1566.71
  text "Symbol" at 4773.39,2101.88 h72
  text "Quantity" at 5074.22,2101.88 h72
  text "Finished Hole Size" at 5406.33,2101.88 h72
  text "Plated" at 6043.34,2101.88 h72
  text "Hole Type" at 6302.69,2101.88 h72
  text "1" at 5074.22,1977.42 h60
  text "10.00mil (0.254mm)" at 5406.33,1977.42 h60
  text "PTH" at 6043.34,1977.42 h60
  text "Round" at 6302.69,1977.42 h60
  text "27" at 5074.22,1852.96 h60
  text "12.00mil (0.305mm)" at 5406.33,1852.96 h60
  text "PTH" at 6043.34,1852.96 h60
  text "Round" at 6302.69,1852.96 h60
  text "12" at 5074.22,1728.5 h60
  text "31.50mil (0.800mm)" at 5406.33,1728.5 h60
  text "PTH" at 6043.34,1728.5 h60
  text "Round" at 6302.69,1728.5 h60
  text "40 Total" at 5074.22,1604.04 h60
  text ".Layer_Name" at 577,-858.49 h60

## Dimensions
1220,522 to 1220,0 on M2 Board Dimensions
0,522 to 1220,522 on M2 Board Dimensions
0,-400 to 1000,-400 on M2 Board Dimensions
